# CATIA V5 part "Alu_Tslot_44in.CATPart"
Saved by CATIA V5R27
Part number: Tslotted_44in
Revision: ANY
Definition: UNKNOWN
Nomenclature: Tslotted_44in
Source: Unknown
Bounding box of the stored display mesh (mm): x -19.056 to 19.056, y -19.056 to 19.056, z -1524 to -404
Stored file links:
  \\triton.meca.polymtl.ca\usagers\zaoue\profiles\Desktop\varm_ass\structure prismatique\Alu_Tslot_44in.CATPart
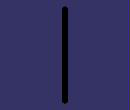
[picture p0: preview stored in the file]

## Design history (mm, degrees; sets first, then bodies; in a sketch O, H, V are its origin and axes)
Body1 "Boss-Extrude1" (main body)
  Solid1: solid without history
  Sketch1 on face of Solid1, origin (0, 0, 1524), H (1, 0, 0), V (0, 1, 0)
    line L1 (-31.855, 32.792) -> (28.107, 32.792)
    line L2 (28.107, 32.792) -> (28.107, -28.509)
    line L3 (28.107, -28.509) -> (-31.855, -28.509)
    line L4 (-31.855, -28.509) -> (-31.855, 32.792)
    horizontal: L1 H, L3 H
    vertical: L2 V, L4 V
    fix: L1, L2, L3, L4
  Pocket1: profile Sketch1, direction (0, 0, -1), length 1928
  Sketch2 on end face of Pocket1, origin (0, 0, -404), H (1, 0, 0), V (0, 1, 0)
    line L1 (19.05, -7.9756) -> (19.05, -9.4996)
    arc A1 centre (19.05, -8.7376) radius 0.762 from (19.05, -7.9756) to (19.05, -9.4996) ccw
    point P3 (19.05, -8.7376)
    reference projected arc E1 centre (19.05, -8.7376) radius 0.762 from (19.05, -7.9756) to (18.288, -8.7376) ccw from edge [end face of Pocket1 | face of Solid1]
    reference projected arc E2 centre (19.05, -8.7376) radius 0.762 from (19.05, -7.9756) to (18.288, -8.7376) ccw from edge [end face of Pocket1 | face of Solid1]
    reference projected arc E3 centre (19.05, -8.7376) radius 0.762 from (19.05, -7.9756) to (18.288, -8.7376) ccw from edge [end face of Pocket1 | face of Solid1]
    line L2 (19.0564, 15.8623) -> (19.0564, 14.3256)
    point P4 (19.0564, 15.0939)
    arc A2 centre (19.0564, 15.0939) radius 0.7684 from (19.0564, 15.8623) to (19.0564, 14.3256) ccw
    line L3 (19.0564, -14.3256) -> (19.0564, -15.8623)
    point P7 (19.0564, -15.0939)
    line L4 (19.05, 9.4996) -> (19.05, 7.9756)
    point P8 (19.05, 8.7376)
    arc A3 centre (19.0564, -15.0939) radius 0.7684 from (19.0564, -14.3256) to (19.0564, -15.8623) ccw
    arc A4 centre (19.05, 8.7376) radius 0.762 from (19.05, 9.4996) to (19.05, 7.9756) ccw
    reference projected arc E4 centre (19.0564, -15.0939) radius 0.7684 from (19.05, -14.3256) to (18.288, -15.0939) ccw from edge [end face of Pocket1 | face of Solid1]
    reference projected arc E5 centre (19.0564, -15.0939) radius 0.7684 from (19.05, -14.3256) to (18.288, -15.0939) ccw from edge [end face of Pocket1 | face of Solid1]
    reference projected arc E6 centre (19.05, 8.7376) radius 0.762 from (19.05, 9.4996) to (18.288, 8.7376) ccw from edge [end face of Pocket1 | face of Solid1]
    reference projected arc E7 centre (19.05, 8.7376) radius 0.762 from (19.05, 9.4996) to (18.288, 8.7376) ccw from edge [end face of Pocket1 | face of Solid1]
    reference projected arc E8 centre (19.0564, 15.0939) radius 0.7684 from (19.05, 15.8623) to (18.288, 15.0939) ccw from edge [end face of Pocket1 | face of Solid1]
    reference projected arc E9 centre (19.0564, 15.0939) radius 0.7684 from (19.05, 15.8623) to (18.288, 15.0939) ccw from edge [end face of Pocket1 | face of Solid1]
    line L5 (14.3256, -19.0563) -> (15.8623, -19.0563)
    arc A5 centre (15.0939, -19.0563) radius 0.7684 from (15.8623, -19.0563) to (14.3256, -19.0563) ccw
    point P15 (15.0939, -19.0563)
    line L6 (-15.8623, -19.0563) -> (-14.3256, -19.0563)
    point P16 (-15.0939, -19.0563)
    arc A6 centre (-15.0939, -19.0563) radius 0.7684 from (-14.3256, -19.0563) to (-15.8623, -19.0563) ccw
    line L7 (7.9756, -19.05) -> (9.4996, -19.05)
    point P19 (8.7376, -19.05)
    arc A7 centre (8.7376, -19.05) radius 0.762 from (9.4996, -19.05) to (7.9756, -19.05) ccw
    line L8 (-9.4996, -19.05) -> (-7.9756, -19.05)
    point P22 (-8.7376, -19.05)
    arc A8 centre (-8.7376, -19.05) radius 0.762 from (-7.9756, -19.05) to (-9.4996, -19.05) ccw
    reference projected arc E10 centre (-15.0939, -19.0563) radius 0.7684 from (-14.3256, -19.05) to (-15.8623, -19.05) ccw from edge [end face of Pocket1 | face of Solid1]
    reference projected arc E11 centre (-15.0939, -19.0563) radius 0.7684 from (-14.3256, -19.05) to (-15.8623, -19.05) ccw from edge [end face of Pocket1 | face of Solid1]
    reference projected arc E12 centre (15.0939, -19.0563) radius 0.7684 from (15.8623, -19.05) to (14.3256, -19.05) ccw from edge [end face of Pocket1 | face of Solid1]
    reference projected arc E13 centre (15.0939, -19.0563) radius 0.7684 from (15.8623, -19.05) to (14.3256, -19.05) ccw from edge [end face of Pocket1 | face of Solid1]
    reference projected arc E14 centre (15.0939, -19.0563) radius 0.7684 from (15.8623, -19.05) to (14.3256, -19.05) ccw from edge [end face of Pocket1 | face of Solid1]
    reference projected arc E15 centre (8.7376, -19.05) radius 0.762 from (9.4996, -19.05) to (7.9756, -19.05) ccw from edge [end face of Pocket1 | face of Solid1]
    reference projected arc E16 centre (8.7376, -19.05) radius 0.762 from (9.4996, -19.05) to (7.9756, -19.05) ccw from edge [end face of Pocket1 | face of Solid1]
    reference projected arc E17 centre (-8.7376, -19.05) radius 0.762 from (-7.9756, -19.05) to (-9.4996, -19.05) ccw from edge [end face of Pocket1 | face of Solid1]
    reference projected arc E18 centre (-8.7376, -19.05) radius 0.762 from (-7.9756, -19.05) to (-9.4996, -19.05) ccw from edge [end face of Pocket1 | face of Solid1]
    construction line L9 (0, 0) -> (35.726, 0)
    construction line L10 (0, 0) -> (0, -21.547)
    radius A1 = 0.762
    radius E3 = 0.762 (reference)
    vertical: L1 V, L2 V, L3 V, L4 V, L10 V
    midpoint: P3 L1, P4 L2, P7 L3, P8 L4, P15 L5, P16 L6, P19 L7, P22 L8
    coincidence: A1 E1, A3 E4, A4 E6, A2 E8, A6 E10, A5 E14, A7 E15, A8 E17
    concentricity: A1 E2, A3 E5, A4 E7, A2 E9, A6 E11, A5 E12, A5 E13, A7 E16, A8 E18
    horizontal: L5 H, L6 H, L7 H, L8 H, L9 H
  Pad1: profile Sketch2, direction (0, 0, -1), up to face of Solid1
  Mirror1: of Pad1, about {plane type Offset, RefPlane face of Solid1, Offset 19.05}
  Mirror2: of Pad1, about {plane type Offset, RefPlane face of Solid1, Offset 19.05}
  Plane1: type Offset, RefPlane face of Pocket1, Offset 559.9938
